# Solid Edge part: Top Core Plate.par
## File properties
Author: davee
Template: Normal.par
Last saved by: davee
Revision: 7
Application: Solid Edge
Accuracy: 0.99
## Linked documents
Core Plate Top.par
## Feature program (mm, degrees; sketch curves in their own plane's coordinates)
part copy "CopiedPart_1"
sketch for "ExtrudedCutout_1" plane through (0, 0, 0) normal (1, 0, 0) x-axis (0, 1, 0)
  line (-25, -6) -> (-3.5607, -0.2553)
  dimension (linear) = 25
extrude "ExtrudedCutout_1" cut finite 70 symmetric
sketch for "ExtrudedCutout_2" plane through (0, 2.945, 0) normal (0, 0, 1) x-axis (1, 0, 0)
  circle centre (0, 1.555) radius 15
extrude "ExtrudedCutout_2" cut finite 5 along -normal
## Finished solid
Body 1: solid body, 28 faces, 47 edges, 14 vertices.
  Faces by surface: plane 15, cylinder 13
  Edges by curve: circle 26, line 21
Bounding box of the edges (mm): 130.000 x 63.110 x 20.000, from (-65, -28.61, -20) to (65, 34.5, 0).
Cylindrical faces by radius (mm): R3.25 x4, R5.5 x4, R6.9175 x1, R8 x2, R10.25 x2
Planar faces by outward normal: +x 2, +y 1, +z 5, -x 2, -y 1, -z 3, oblique 1
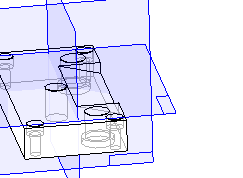
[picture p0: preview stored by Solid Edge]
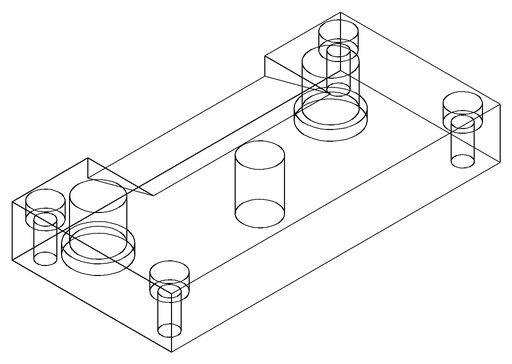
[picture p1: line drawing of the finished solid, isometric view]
